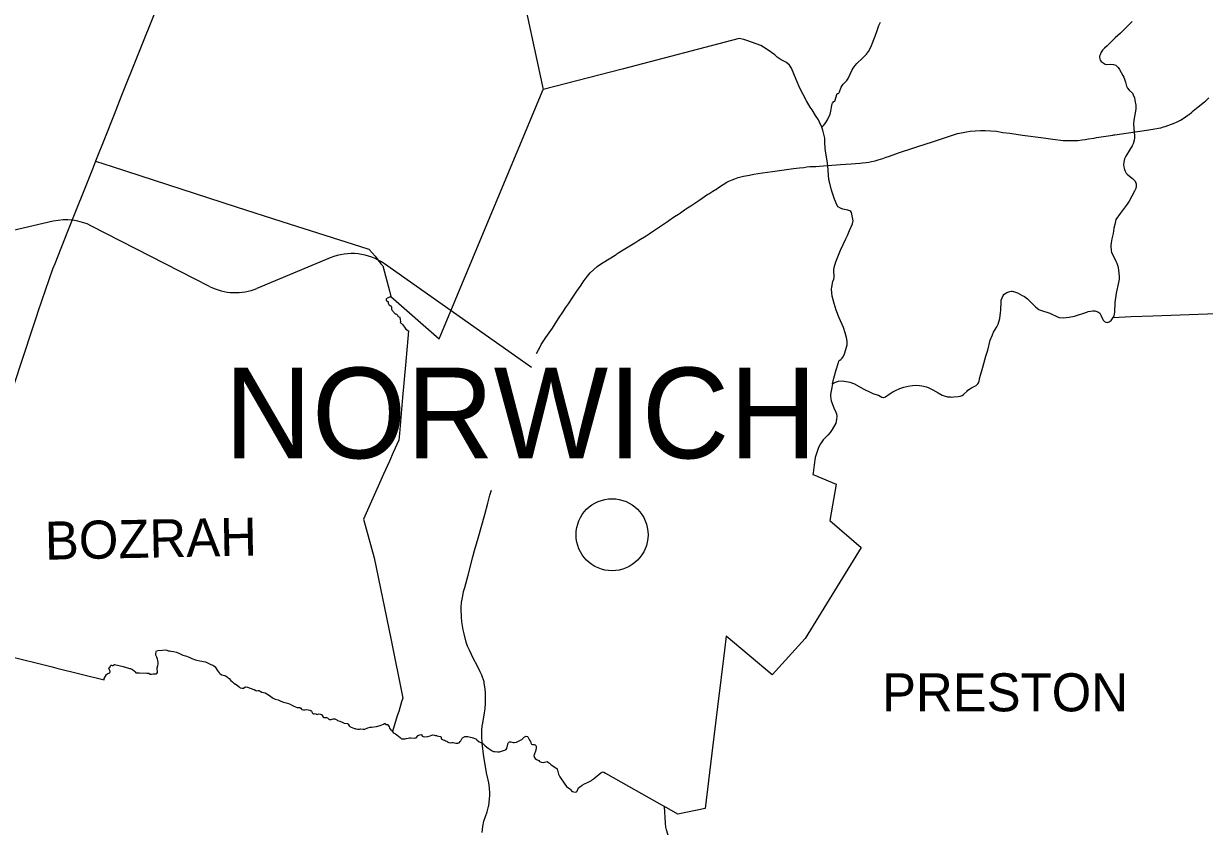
# Model space of a CAD drawing. Extents: x 0 to 2603, y -226 to 830.
# Drawn here: x 287.25 to 329.14, y 575 to 603.47 of the extents above; entities that cross this region are included whole.
import ezdxf

# ---------------------------------------------------------------- set-up
doc = ezdxf.new("R2010")
doc.units = 0
for name, color, linetype in [('CT_TSH_Map_Cities_Text', 7, 'Continuous'), ('CT_TSH_Map_Interstate_Roads', 7, 'Continuous'), ('CT_TSH_Map_Town_Limits', 7, 'Continuous'), ('CT_TSH_Map_Town_Text', 7, 'Continuous'), ('CT_TSH_Map_US_and_State_Routes', 7, 'Continuous')]:
    doc.layers.add(name, color=color, linetype=linetype)

msp = doc.modelspace()

# ---------------------------------------------------------------- linework, layer by layer
at = {"layer": 'CT_TSH_Map_Cities_Text'}
msp.add_circle((308.128, 585.339), 1.277, dxfattribs=at)
at = {"layer": 'CT_TSH_Map_Interstate_Roads'}
for points in [[(328.928, 600.519), (329.144, 600.689), (329.181, 600.72), (329.298, 600.838)], [(328.696, 600.332), (328.748, 600.378), (328.804, 600.42)], [(328.804, 600.42), (328.928, 600.519)], [(327.983, 599.897), (328.077, 599.935), (328.176, 599.982), (328.3, 600.047), (328.397, 600.105), (328.478, 600.159), (328.555, 600.216), (328.601, 600.251), (328.696, 600.332)], [(319.82, 599.384), (320.316, 599.547)], [(320.316, 599.547), (320.39, 599.57), (320.591, 599.61), (320.699, 599.631), (320.832, 599.652), (321.009, 599.669), (321.203, 599.68), (321.369, 599.68), (321.562, 599.671), (321.771, 599.649), (321.998, 599.611), (322.247, 599.579), (322.693, 599.518), (323.434, 599.418), (323.768, 599.37)], [(325.932, 599.523), (325.962, 599.53)], [(325.962, 599.53), (327.169, 599.705)], [(327.169, 599.705), (327.383, 599.736)], [(327.383, 599.736), (327.52, 599.762), (327.597, 599.778), (327.689, 599.802)], [(327.689, 599.802), (327.759, 599.821), (327.853, 599.852)], [(327.853, 599.852), (327.983, 599.897)], [(318.98, 599.108), (319.501, 599.281)], [(319.501, 599.281), (319.82, 599.384)], [(323.768, 599.37), (324.135, 599.328), (324.253, 599.321)], [(324.253, 599.321), (324.396, 599.319), (324.52, 599.32), (324.656, 599.328), (324.805, 599.344), (324.909, 599.357), (325.031, 599.379)], [(325.031, 599.379), (325.234, 599.411)], [(325.234, 599.411), (325.312, 599.425)], [(325.312, 599.425), (325.891, 599.518)], [(325.891, 599.518), (325.932, 599.523)], [(315.763, 598.431), (316.091, 598.458), (316.23, 598.468), (316.615, 598.497), (316.916, 598.52), (317.011, 598.527), (317.142, 598.544), (317.239, 598.559), (317.333, 598.577), (317.462, 598.607), (317.568, 598.635), (317.737, 598.688), (317.856, 598.732), (317.971, 598.773), (318.325, 598.895)], [(318.325, 598.895), (318.367, 598.904), (318.763, 599.036), (318.98, 599.108)], [(313.462, 598.172), (313.819, 598.222), (314.401, 598.302)], [(314.401, 598.302), (314.561, 598.325)], [(314.561, 598.325), (314.783, 598.356), (314.937, 598.367), (315.042, 598.389)], [(315.042, 598.389), (315.149, 598.395), (315.338, 598.399), (315.358, 598.395)], [(315.358, 598.395), (315.485, 598.407)], [(315.485, 598.407), (315.628, 598.42)], [(315.628, 598.42), (315.763, 598.431)], [(312.205, 597.844), (312.272, 597.877), (312.393, 597.93), (312.48, 597.964), (312.598, 598.005), (312.79, 598.053), (313.005, 598.097), (313.154, 598.124), (313.462, 598.172)], [(311.532, 597.414), (311.564, 597.426), (311.706, 597.521), (311.843, 597.608), (311.909, 597.652), (312.075, 597.76), (312.205, 597.844)], [(310.349, 596.622), (310.481, 596.712), (310.551, 596.759), (310.701, 596.861), (310.805, 596.929), (310.923, 597.009), (311.033, 597.081), (311.098, 597.125), (311.206, 597.197), (311.322, 597.274), (311.411, 597.333), (311.532, 597.414)], [(308.584, 595.482), (308.762, 595.591), (308.937, 595.698), (309.083, 595.787), (309.333, 595.94), (309.442, 596.015), (309.596, 596.118), (309.7, 596.187), (309.815, 596.265), (309.951, 596.356), (310.093, 596.451), (310.145, 596.487), (310.349, 596.622)], [(308.275, 595.283), (308.299, 595.307), (308.371, 595.352), (308.465, 595.408), (308.584, 595.482)], [(307.028, 594.194), (307.132, 594.35), (307.181, 594.42), (307.26, 594.515), (307.353, 594.626), (307.605, 594.849), (307.644, 594.885), (307.815, 594.992), (308.023, 595.121), (308.24, 595.258), (308.275, 595.283)], [(306.739, 593.769), (306.879, 593.974), (306.939, 594.065), (307.028, 594.194)], [(305.449, 591.77), (305.515, 591.893), (305.55, 591.959), (305.617, 592.087), (305.78, 592.331), (306.011, 592.672), (306.229, 593.005), (306.404, 593.272), (306.479, 593.39), (306.578, 593.534), (306.739, 593.769)], [(302.906, 583.474), (303.021, 583.907), (303.189, 584.553), (303.25, 584.781), (303.374, 585.219), (303.609, 586.054), (303.724, 586.464), (303.794, 586.741), (303.847, 586.925)], [(302.782, 582.483), (302.777, 582.641), (302.779, 582.775), (302.791, 582.939), (302.829, 583.168), (302.861, 583.329), (302.906, 583.474)], [(302.947, 581.525), (302.875, 581.82), (302.842, 581.963), (302.794, 582.254), (302.791, 582.42), (302.782, 582.483)], [(303.001, 581.392), (302.947, 581.525)], [(303.216, 580.943), (303.064, 581.25), (303.001, 581.392)], [(303.339, 580.702), (303.216, 580.943)], [(303.607, 579.999), (303.591, 580.085), (303.585, 580.127), (303.504, 580.356), (303.484, 580.412), (303.45, 580.48), (303.339, 580.702)], [(303.539, 578.658), (303.607, 579.028), (303.625, 579.168), (303.639, 579.368), (303.636, 579.715), (303.623, 579.875)], [(303.623, 579.875), (303.607, 579.999)], [(303.522, 577.949), (303.513, 578.204), (303.513, 578.415), (303.52, 578.545), (303.539, 578.658)], [(303.698, 576.801), (303.688, 576.82), (303.576, 577.473), (303.549, 577.654), (303.522, 577.949)], [(303.795, 576.169), (303.783, 576.361), (303.757, 576.545), (303.698, 576.801)], [(303.765, 575.843), (303.783, 575.973), (303.796, 576.088), (303.795, 576.169)], [(303.633, 575.351), (303.693, 575.517), (303.74, 575.704)], [(303.74, 575.704), (303.75, 575.738), (303.765, 575.843)], [(303.519, 574.784), (303.546, 574.99), (303.584, 575.181), (303.633, 575.351)]]:
    msp.add_lwpolyline(points, dxfattribs=at)
at = {"layer": 'CT_TSH_Map_Town_Limits'}
for points in [[(302.713, 615.444), (303.32, 612.429), (303.8, 610.105), (304.295, 607.665), (304.396, 607.18), (304.478, 606.851), (304.826, 605.141), (305.685, 601.128)], [(296.081, 614.448), (295.587, 613.21), (294.832, 611.275), (294.647, 610.824), (294.281, 609.854), (294.094, 609.418), (293.047, 606.773), (292.726, 605.95), (292.497, 605.371), (292.283, 604.813), (291.932, 603.919), (290.701, 600.858), (290.464, 600.245), (290.142, 599.44), (289.803, 598.588)], [(315.573, 599.794), (315.63, 599.85), (315.689, 599.924), (315.773, 600.054), (315.864, 600.255), (315.891, 600.358), (315.911, 600.51), (315.941, 600.621), (315.95, 600.643), (315.999, 600.701), (316.028, 600.714), (316.119, 600.989), (316.153, 600.989), (316.172, 601.002), (316.197, 601.053), (316.258, 601.211), (316.333, 601.323), (316.454, 601.455), (316.503, 601.522), (316.571, 601.681), (316.642, 601.828), (316.68, 601.888), (316.75, 601.986), (316.814, 602.058), (317.009, 602.243), (317.058, 602.285), (317.155, 602.387), (317.227, 602.484), (317.31, 602.637), (317.459, 603.028), (317.536, 603.223), (317.599, 603.401), (317.657, 603.526)], [(326.581, 603.54), (326.405, 603.361), (326.356, 603.319), (326.169, 603.135), (325.985, 602.962), (325.694, 602.685), (325.595, 602.603), (325.531, 602.53), (325.486, 602.461), (325.442, 602.367), (325.429, 602.315), (325.428, 602.265), (325.451, 602.175), (325.482, 602.131), (325.517, 602.098), (325.588, 602.052), (325.627, 602.034), (325.672, 602.02), (325.83, 602.03), (325.926, 602.019), (325.998, 601.994), (326.014, 601.984), (326.08, 601.911), (326.135, 601.845), (326.255, 601.63), (326.283, 601.571), (326.345, 601.392), (326.382, 601.249), (326.418, 601.176), (326.476, 601.104), (326.59, 600.998), (326.623, 600.946), (326.663, 600.841), (326.682, 600.762), (326.682, 600.747), (326.709, 600.572), (326.71, 600.431), (326.638, 600.049), (326.63, 599.906), (326.641, 599.748), (326.669, 599.483), (326.667, 599.403), (326.656, 599.33), (326.619, 599.206), (326.587, 599.137), (326.49, 598.977), (326.355, 598.769), (326.309, 598.671), (326.284, 598.556), (326.278, 598.464), (326.282, 598.385), (326.306, 598.294), (326.331, 598.231), (326.367, 598.17), (326.403, 598.132), (326.545, 598.014), (326.599, 597.975), (326.687, 597.877), (326.706, 597.85), (326.725, 597.788), (326.728, 597.7), (326.71, 597.626), (326.664, 597.528), (326.48, 597.169)], [(315.573, 599.794), (315.489, 599.974), (315.451, 600.054), (315.352, 600.204), (315.228, 600.407), (315.157, 600.508), (315.03, 600.725), (314.791, 601.179), (314.659, 601.488), (314.496, 601.886), (314.45, 601.958), (314.42, 601.995), (314.332, 602.079), (314.293, 602.107), (314.131, 602.184), (314.018, 602.258), (313.989, 602.28), (313.908, 602.36), (313.626, 602.55), (313.406, 602.69), (312.906, 602.873), (312.807, 602.901), (312.633, 602.941), (308.484, 601.858), (305.685, 601.128)], [(300.282, 593.79), (301.99, 592.285), (302.111, 592.568), (305.685, 601.128)], [(315.955, 590.69), (315.997, 590.894), (316.077, 591.184), (316.157, 591.45), (316.18, 591.501), (316.192, 591.518), (316.248, 591.553), (316.294, 591.604), (316.318, 591.639), (316.362, 591.72), (316.392, 591.794), (316.448, 591.989), (316.469, 592.078), (316.471, 592.146), (316.466, 592.209), (316.444, 592.33), (316.401, 592.504), (316.343, 592.688), (316.182, 593.028), (316.085, 593.31), (316.005, 593.542), (315.937, 593.806), (315.922, 593.921), (315.917, 594.045), (315.924, 594.121), (315.962, 594.317), (315.994, 594.409), (316.008, 594.467), (316.011, 594.527), (315.992, 594.674), (315.994, 594.735), (316.005, 594.823), (316.067, 595.024), (316.238, 595.434), (316.424, 595.84), (316.477, 595.95), (316.552, 596.131), (316.654, 596.364), (316.674, 596.429), (316.678, 596.474), (316.62, 596.768), (316.596, 596.807), (316.562, 596.831), (316.496, 596.854), (316.313, 596.886), (316.229, 596.919), (316.152, 596.974), (316.12, 597.014), (316.019, 597.244), (315.915, 597.566), (315.838, 597.855), (315.822, 597.939), (315.784, 598.43), (315.759, 598.601), (315.715, 598.872), (315.707, 598.957), (315.695, 599.037), (315.679, 599.261), (315.678, 599.338), (315.674, 599.409), (315.607, 599.685), (315.573, 599.794)], [(289.803, 598.588), (289.688, 598.309), (288.801, 596.091), (288.352, 594.945), (288.276, 594.762), (287.754, 593.241), (287.72, 593.124), (287.551, 592.637), (286.557, 589.62), (286.471, 589.362), (286.336, 588.939), (285.92, 587.694), (285.563, 586.765), (285.469, 586.545)], [(289.803, 598.588), (290.39, 598.396), (294.796, 596.971), (296.415, 596.449), (299.202, 595.567), (299.501, 595.466), (299.513, 595.46), (299.727, 595.218), (299.928, 594.945), (299.989, 594.872), (300.235, 593.986), (300.282, 593.79)], [(326.48, 597.169), (326.404, 597.059), (326.299, 596.927), (326.194, 596.781), (326.152, 596.729), (326.007, 596.52), (325.963, 596.34), (325.934, 596.212), (325.905, 596.019), (325.865, 595.834), (325.839, 595.698), (325.824, 595.589), (325.832, 595.408), (325.848, 595.359), (326.008, 595.049), (326.04, 594.975), (326.074, 594.871), (326.103, 594.73), (326.126, 594.492), (326.123, 594.399), (326.115, 594.35), (326.097, 594.284), (326.02, 593.904), (325.967, 593.574), (325.959, 593.233), (325.928, 593.108), (325.906, 593.043)], [(300.282, 593.79), (300.247, 593.761), (300.145, 593.734), (300.119, 593.711), (300.11, 593.695), (300.115, 593.653), (300.131, 593.635), (300.171, 593.617), (300.186, 593.598), (300.188, 593.557), (300.213, 593.511), (300.246, 593.479), (300.285, 593.443), (300.307, 593.406), (300.308, 593.344), (300.31, 593.314), (300.326, 593.288), (300.369, 593.25), (300.386, 593.218), (300.432, 593.18), (300.458, 593.17), (300.483, 593.162), (300.511, 593.128), (300.527, 593.096), (300.541, 593.083), (300.569, 593.072), (300.582, 593.064), (300.599, 593.036), (300.614, 592.977), (300.618, 592.907), (300.616, 592.893), (300.614, 592.868), (300.624, 592.858), (300.647, 592.849), (300.701, 592.785), (300.782, 592.669), (300.816, 592.628), (300.909, 592.572), (300.798, 591.36), (300.697, 590.213), (300.587, 588.936), (300.562, 588.699), (300.361, 588.251), (300.228, 587.954), (300.013, 587.487), (299.303, 585.897), (299.686, 584.525), (300.278, 581.656), (300.71, 579.549), (300.663, 579.415), (300.56, 579.074), (300.507, 578.916), (300.343, 578.36)], [(315.955, 590.69), (316.055, 590.754), (316.097, 590.769), (316.158, 590.784), (316.295, 590.793), (316.367, 590.792), (316.503, 590.769), (316.567, 590.751), (316.725, 590.69), (317.039, 590.516), (317.31, 590.387), (317.381, 590.345), (317.447, 590.322), (317.581, 590.287), (317.705, 590.222), (317.759, 590.204), (317.777, 590.206), (317.83, 590.231), (317.959, 590.331), (318.096, 590.413), (318.186, 590.45), (318.341, 590.526), (318.477, 590.572), (318.631, 590.611), (318.792, 590.631), (318.88, 590.642), (319.04, 590.636), (319.119, 590.625), (319.287, 590.582), (319.372, 590.548), (319.505, 590.484), (319.694, 590.368), (319.846, 590.293), (319.911, 590.269), (320.032, 590.237), (320.136, 590.228), (320.189, 590.225), (320.251, 590.234), (320.414, 590.245), (320.475, 590.259), (320.546, 590.281), (320.599, 590.315), (320.621, 590.342), (320.723, 590.438), (320.75, 590.465), (320.882, 590.553), (321.044, 590.636), (321.106, 590.695), (321.132, 590.726), (321.155, 590.783), (321.171, 590.86), (321.177, 590.922), (321.279, 591.28), (321.395, 591.671), (321.463, 591.888), (321.544, 592.239), (321.623, 592.435), (321.668, 592.528), (321.778, 592.712), (321.823, 592.807), (321.885, 593.015), (321.913, 593.206), (321.922, 593.309), (321.93, 593.602), (321.938, 593.656), (321.964, 593.744), (322.002, 593.828), (322.033, 593.865), (322.071, 593.895), (322.133, 593.928), (322.244, 593.971), (322.291, 593.978), (322.322, 593.977), (322.371, 593.967), (322.516, 593.916), (322.681, 593.828), (322.76, 593.785), (322.866, 593.705), (322.938, 593.641), (323.151, 593.423), (323.209, 593.372), (323.27, 593.333), (323.331, 593.302), (323.666, 593.201), (323.961, 593.056), (323.996, 593.046), (324.13, 593.038), (324.345, 593.053), (324.533, 593.093), (324.971, 593.238), (325.024, 593.255), (325.181, 593.282), (325.253, 593.279), (325.33, 593.256), (325.36, 593.245), (325.433, 593.197), (325.469, 593.133), (325.538, 592.971), (325.555, 592.947), (325.604, 592.901), (325.654, 592.875)], [(325.906, 593.043), (326.547, 593.076), (327.314, 593.1), (329.577, 593.191), (331.802, 593.271), (332.109, 593.286), (332.428, 592.906), (332.726, 592.569), (335.142, 589.762), (336.091, 588.665), (338.483, 585.886), (339.715, 584.457), (340.889, 583.091), (341.356, 582.551)], [(325.654, 592.875), (325.693, 592.87), (325.761, 592.896), (325.834, 592.939), (325.864, 592.973), (325.906, 593.043)], [(315.955, 590.69), (315.91, 590.504), (315.899, 590.44), (315.883, 590.312), (315.883, 590.252), (315.89, 590.163), (315.908, 590.087), (315.994, 589.846), (316.072, 589.693), (316.091, 589.633), (316.098, 589.544), (316.094, 589.422), (316.063, 589.296), (315.939, 589.069), (315.868, 588.967), (315.79, 588.877), (315.621, 588.707), (315.57, 588.639), (315.529, 588.568), (315.458, 588.432), (315.401, 588.297), (315.356, 588.152), (315.34, 588.075), (315.297, 587.818), (315.267, 587.538), (315.252, 587.472), (315.381, 587.425), (315.426, 587.4), (316.074, 587.133), (315.858, 585.843), (316.968, 584.883), (314.978, 581.656), (313.805, 580.369), (312.176, 581.739), (312.113, 581.251), (311.872, 579.232), (311.674, 577.587), (311.427, 575.626), (310.463, 575.426), (309.983, 575.699)], [(286.642, 581.061), (288.26, 580.652), (288.43, 580.613), (290.106, 580.196), (290.111, 580.238), (290.187, 580.382), (290.205, 580.398), (290.237, 580.414), (290.27, 580.425), (290.314, 580.454), (290.323, 580.473), (290.325, 580.488), (290.31, 580.528), (290.281, 580.574), (290.272, 580.609), (290.282, 580.628), (290.316, 580.653), (290.346, 580.711), (290.367, 580.716), (290.39, 580.701), (290.409, 580.705), (290.476, 580.736), (290.776, 580.662), (291.001, 580.593), (291.038, 580.59), (291.065, 580.584), (291.117, 580.559), (291.169, 580.517), (291.208, 580.475), (291.227, 580.445), (291.27, 580.439), (291.361, 580.443), (291.621, 580.43), (291.691, 580.424), (291.745, 580.394), (291.785, 580.393), (291.845, 580.407), (291.908, 580.411), (291.949, 580.41), (291.98, 580.419), (292, 580.454), (291.99, 580.62), (292.008, 580.696), (292.023, 580.75), (292.024, 580.803), (292.012, 580.874), (291.995, 580.929), (291.98, 580.993), (291.941, 581.073), (291.94, 581.115), (291.949, 581.188), (291.948, 581.201), (291.963, 581.218), (292.008, 581.234), (292.172, 581.241), (292.279, 581.256), (292.326, 581.248), (292.374, 581.225), (292.41, 581.218), (292.424, 581.219), (292.472, 581.206), (292.57, 581.198), (292.674, 581.174), (292.801, 581.113), (292.901, 581.074), (292.993, 581.046), (293.126, 580.993), (293.216, 580.951), (293.35, 580.9), (293.392, 580.895), (293.497, 580.869), (293.701, 580.831), (293.797, 580.787), (293.89, 580.734), (293.959, 580.712), (293.997, 580.692), (294.043, 580.649), (294.117, 580.531), (294.185, 580.437), (294.224, 580.404), (294.283, 580.375), (294.371, 580.347), (294.418, 580.338), (294.472, 580.299), (294.507, 580.26), (294.538, 580.235), (294.602, 580.166), (294.657, 580.128), (294.71, 580.078), (294.823, 580.01), (294.899, 579.951), (294.93, 579.914), (294.999, 579.894), (295.048, 579.9), (295.103, 579.937), (295.12, 579.943)], [(295.12, 579.943), (295.19, 579.928), (295.388, 579.863), (295.433, 579.851), (295.489, 579.811), (295.515, 579.804), (295.576, 579.821), (295.6, 579.814), (295.637, 579.788), (295.702, 579.756), (295.82, 579.735), (295.934, 579.663), (296.018, 579.598), (296.067, 579.572), (296.108, 579.545), (296.127, 579.533), (296.179, 579.509), (296.279, 579.485), (296.328, 579.465), (296.372, 579.44), (296.467, 579.402), (296.559, 579.379), (296.653, 579.349), (296.707, 579.335), (296.794, 579.279), (296.838, 579.257), (296.951, 579.217), (296.988, 579.211), (297.044, 579.21), (297.081, 579.187), (297.109, 579.15), (297.124, 579.137), (297.176, 579.124), (297.228, 579.13), (297.285, 579.142), (297.401, 579.118), (297.415, 579.109), (297.438, 579.106), (297.463, 579.077), (297.499, 579.006), (297.506, 578.997), (297.531, 578.988), (297.564, 578.989), (297.594, 578.995), (297.639, 578.979), (297.667, 578.969), (297.726, 578.984), (297.78, 578.978), (297.815, 578.963), (297.84, 578.934), (297.879, 578.87), (297.906, 578.859), (297.991, 578.852), (298.029, 578.842), (298.054, 578.824), (298.075, 578.794), (298.097, 578.782), (298.159, 578.787), (298.231, 578.806), (298.286, 578.807), (298.358, 578.769), (298.387, 578.754), (298.467, 578.733), (298.547, 578.694), (298.596, 578.663), (298.622, 578.654), (298.727, 578.645), (298.749, 578.642), (298.768, 578.626), (298.804, 578.567), (298.829, 578.543), (298.872, 578.514), (298.991, 578.466), (299.018, 578.462), (299.04, 578.451), (299.102, 578.441), (299.165, 578.441), (299.208, 578.452), (299.299, 578.438), (299.358, 578.449), (299.463, 578.496), (299.548, 578.509), (299.596, 578.511), (299.765, 578.536), (299.898, 578.568), (300.014, 578.622), (300.052, 578.642), (300.071, 578.641), (300.085, 578.627), (300.09, 578.62), (300.105, 578.613), (300.159, 578.615), (300.177, 578.597), (300.194, 578.558), (300.215, 578.528), (300.237, 578.476), (300.264, 578.437), (300.3, 578.409), (300.32, 578.379), (300.343, 578.36)], [(300.343, 578.36), (300.364, 578.328), (300.399, 578.302), (300.45, 578.278), (300.494, 578.246), (300.612, 578.147), (300.648, 578.112), (300.661, 578.103), (300.73, 578.095), (300.785, 578.103), (300.825, 578.116), (300.888, 578.124), (300.94, 578.139), (300.993, 578.14), (301.117, 578.126), (301.177, 578.134), (301.253, 578.218), (301.278, 578.235), (301.34, 578.257), (301.362, 578.242), (301.392, 578.205), (301.429, 578.185), (301.49, 578.176), (301.589, 578.18), (301.68, 578.209), (301.729, 578.233), (301.765, 578.237), (301.83, 578.227), (301.852, 578.221), (301.896, 578.214), (301.923, 578.208), (301.968, 578.19), (302.044, 578.178), (302.061, 578.161), (302.065, 578.146), (302.06, 578.114), (302.069, 578.096), (302.131, 578.067), (302.138, 578.061), (302.184, 578.055), (302.216, 578.029), (302.265, 578.021), (302.283, 578.012), (302.318, 577.984), (302.34, 577.975), (302.401, 577.964), (302.439, 577.969), (302.491, 577.971), (302.58, 577.951), (302.654, 577.949), (302.698, 577.961), (302.743, 578.005), (302.763, 578.032), (302.807, 578.125), (302.821, 578.14), (302.906, 578.178), (302.934, 578.178), (302.971, 578.186), (303.012, 578.185), (303.061, 578.175), (303.157, 578.153), (303.294, 578.096), (303.33, 578.07), (303.409, 577.998), (303.526, 577.948), (303.551, 577.928), (303.623, 577.857), (303.733, 577.772), (303.877, 577.677), (303.923, 577.657), (303.963, 577.649), (304.064, 577.635), (304.134, 577.643), (304.347, 577.712), (304.367, 577.723), (304.394, 577.758), (304.399, 577.791), (304.413, 577.835), (304.428, 577.925), (304.449, 577.966), (304.465, 577.979), (304.494, 577.992), (304.542, 577.991), (304.616, 577.971), (304.658, 577.968), (304.736, 577.984), (304.803, 578.013), (304.921, 578.079), (305.02, 578.171), (305.051, 578.188), (305.067, 578.192), (305.122, 578.181), (305.143, 578.167), (305.182, 578.081), (305.203, 578.053), (305.229, 578.004), (305.241, 577.96), (305.269, 577.907), (305.301, 577.894), (305.362, 577.899), (305.398, 577.886)], [(305.398, 577.886), (305.422, 577.866), (305.432, 577.84), (305.438, 577.783), (305.418, 577.696), (305.359, 577.537), (305.356, 577.504), (305.37, 577.452), (305.4, 577.405), (305.45, 577.366), (305.528, 577.331), (305.557, 577.302), (305.609, 577.277), (305.68, 577.266), (305.734, 577.274), (305.78, 577.29), (305.821, 577.296), (305.839, 577.286), (305.905, 577.234), (305.952, 577.191), (305.987, 577.168), (306.175, 577.04), (306.224, 576.844), (306.276, 576.757), (306.452, 576.492), (306.51, 576.411), (306.555, 576.377), (306.586, 576.36), (306.633, 576.327), (306.65, 576.302), (306.687, 576.261), (306.728, 576.237), (306.777, 576.22), (306.834, 576.214), (306.868, 576.225), (306.889, 576.244), (306.923, 576.336), (306.943, 576.362), (306.986, 576.393), (307.01, 576.405), (307.073, 576.456), (307.151, 576.505), (307.257, 576.553), (307.397, 576.628), (307.429, 576.653), (307.503, 576.705), (307.531, 576.732), (307.728, 576.892), (307.783, 576.923), (307.808, 576.925), (307.841, 576.916), (307.894, 576.886), (309.983, 575.699)], [(312.19, 569.304), (312.12, 569.539), (311.997, 569.924), (311.831, 570.405), (311.546, 571.267), (311.397, 572.164), (311.364, 572.29), (311.313, 572.454), (311.02, 573.295), (310.998, 573.336), (310.943, 573.45), (310.891, 573.542), (310.799, 573.656), (310.552, 573.955), (310.391, 574.139), (310.265, 574.3), (310.202, 574.411), (310.161, 574.53), (310.062, 574.871), (310.038, 574.963), (310.022, 575.107), (309.983, 575.699)]]:
    msp.add_lwpolyline(points, dxfattribs=at)
at = {"layer": 'CT_TSH_Map_US_and_State_Routes'}
for p, q in [((288.303, 596.458), (280.795, 594.734)), ((293.849, 594.145), (289.662, 596.289)), ((298.131, 595.161), (295.528, 594.079)), ((305.274, 591.267), (300.051, 594.949))]:
    msp.add_line(p, q, dxfattribs=at)
for centre, start, end in [((288.75, 594.508), 62.8947, 102.9326), ((298.899, 593.314), 54.8224, 112.5681), ((294.761, 595.926), 242.8947, 292.5681)]:
    msp.add_arc(centre, 2, start, end, dxfattribs=at)

# ---------------------------------------------------------------- texts
at = {"layer": 'CT_TSH_Map_Cities_Text'}
msp.add_text('NORWICH', height=3.2147, rotation=360, dxfattribs=at).set_placement((294.377, 588.052))
at = {"layer": 'CT_TSH_Map_Town_Text'}
msp.add_text('BOZRAH', height=1.35, rotation=1.1627, dxfattribs=at).set_placement((288.016, 584.452))
msp.add_text('PRESTON', height=1.35, dxfattribs=at).set_placement((317.708, 579.075))

doc.saveas('drawing.dxf')
